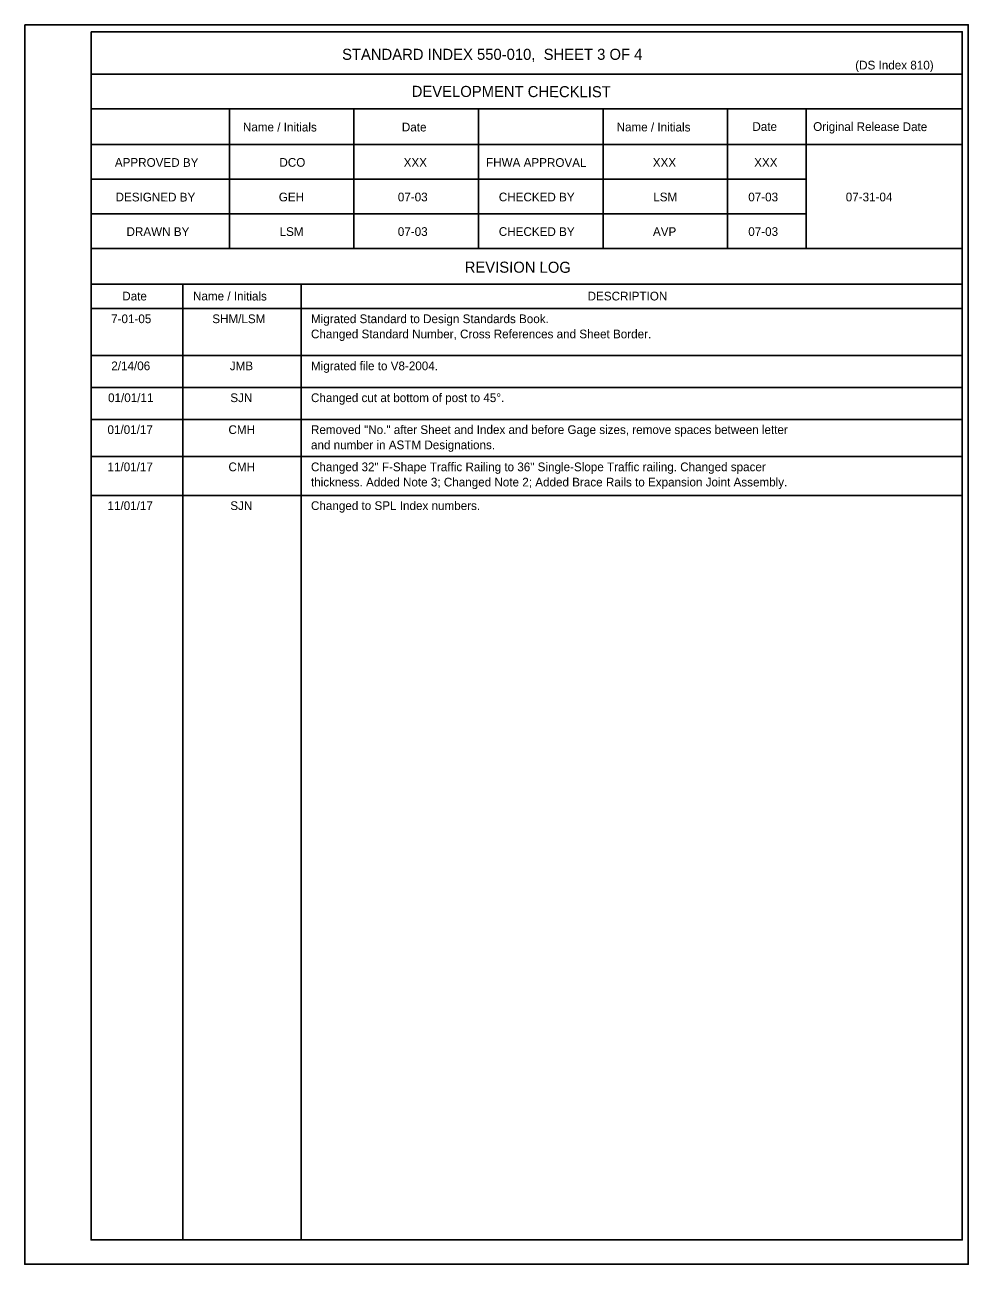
# Model space of a CAD drawing. Extents: x 0 to 72.1, y -7 to 30.
# Drawn here: x 50.31 to 72.12, y -0.65 to 28.01 of the extents above; entities that cross this region are included whole.
import ezdxf

# ---------------------------------------------------------------- set-up
doc = ezdxf.new("R2010")
doc.units = 0
for name, color, linetype in [('Border', 7, 'Continuous'), ('PlotBorder_dp', 7, 'Continuous'), ('TextStructures', 7, 'Continuous')]:
    doc.layers.add(name, color=color, linetype=linetype)

msp = doc.modelspace()

# ---------------------------------------------------------------- linework, layer by layer
at = {"layer": 'Border'}
for p, q in [((71.988, 26.871), (51.841, 26.871)), ((71.988, 26.071), (51.841, 26.071)), ((55.041, 26.071), (55.041, 22.843)), ((57.921, 26.071), (57.921, 22.843)), ((60.801, 26.071), (60.801, 22.843)), ((63.681, 26.071), (63.681, 22.843)), ((66.561, 26.071), (66.561, 22.843)), ((68.376, 26.071), (68.376, 22.843)), ((71.988, 25.243), (51.841, 25.243)), ((68.376, 24.443), (51.841, 24.443)), ((68.376, 23.643), (51.841, 23.643)), ((71.988, 22.843), (51.841, 22.843)), ((71.988, 22.015), (51.841, 22.015)), ((53.962, 22.015), (53.962, -0.091)), ((56.704, 22.015), (56.704, -0.091)), ((71.988, 21.451), (51.841, 21.451)), ((71.988, 20.362), (51.841, 20.362)), ((71.988, 19.625), (51.841, 19.625)), ((71.988, 18.887), (51.841, 18.887)), ((71.988, 18.026), (51.841, 18.026)), ((71.988, 17.129), (51.841, 17.129))]:
    msp.add_line(p, q, dxfattribs=at)
msp.add_lwpolyline([(51.842, 27.851), (71.988, 27.851), (71.988, -0.091), (51.842, -0.091)], close=True, dxfattribs=at)
at = {"layer": 'PlotBorder_dp'}
msp.add_line((50.311, -0.653), (50.311, -0.653), dxfattribs=at)
msp.add_lwpolyline([(50.311, 28.014), (72.124, 28.014), (72.124, -0.653), (50.311, -0.653)], close=True, dxfattribs=at)

# ---------------------------------------------------------------- texts
at = {"layer": 'TextStructures'}
for s, height, p in [('STANDARD INDEX 550-010,  SHEET 3 OF 4', 0.256, (57.647, 27.203)), ('(DS Index 810)', 0.2016, (69.512, 26.98)), ('DCO', 0.2016, (56.198, 24.73)), ('XXX', 0.2016, (59.071, 24.73)), ('XXX', 0.2016, (64.831, 24.73)), ('XXX', 0.2016, (67.175, 24.73)), ('GEH', 0.2016, (56.184, 23.93)), ('07-03', 0.2016, (58.936, 23.93)), ('LSM', 0.2016, (64.842, 23.93)), ('07-03', 0.2016, (67.039, 23.93)), ('07-31-04', 0.2016, (69.293, 23.93)), ('LSM', 0.2016, (56.202, 23.13)), ('07-03', 0.2016, (58.936, 23.13)), ('AVP', 0.2016, (64.835, 23.13)), ('07-03', 0.2016, (67.039, 23.13)), ('DESCRIPTION', 0.2016, (63.325, 21.638)), ('7-01-05', 0.2016, (52.307, 21.113)), ('SHM/LSM', 0.2016, (54.646, 21.113)), ('Migrated Standard to Design Standards Book.', 0.2016, (56.928, 21.113)), ('Changed Standard Number, Cross References and Sheet Border.', 0.2016, (56.928, 20.762)), ('2/14/06', 0.2016, (52.311, 20.024)), ('JMB', 0.2016, (55.051, 20.024)), ('Migrated file to V8-2004.', 0.2016, (56.928, 20.024)), ('01/01/11', 0.2016, (52.236, 19.287)), ('Changed cut at bottom of post to 45°.', 0.2016, (56.928, 19.287)), ('SJN', 0.2016, (55.063, 19.287)), ('01/01/17', 0.2016, (52.223, 18.549)), ('CMH', 0.2016, (55.02, 18.549)), ('Removed "No." after Sheet and Index and before Gage sizes, remove spaces between letter', 0.2016, (56.928, 18.549)), ('and number in ASTM Designations.', 0.2016, (56.928, 18.197)), ('11/01/17', 0.2016, (52.223, 17.688)), ('CMH', 0.2016, (55.02, 17.688)), ('Changed 32" F-Shape Traffic Railing to 36" Single-Slope Traffic railing. Changed spacer', 0.2016, (56.928, 17.688)), ('thickness. Added Note 3; Changed Note 2; Added Brace Rails to Expansion Joint Assembly.', 0.2016, (56.928, 17.336)), ('11/01/17', 0.2016, (52.223, 16.791)), ('SJN', 0.2016, (55.063, 16.791)), ('Changed to SPL Index numbers.', 0.2016, (56.928, 16.791))]:
    msp.add_text(s, height=height, dxfattribs=at).set_placement(p)
for s, height, p in [('DEVELOPMENT CHECKLIST', 0.256, (59.257, 26.347)), ('Name / Initials', 0.2016, (55.354, 25.55)), ('Date', 0.2016, (59.029, 25.548)), ('Name / Initials', 0.2016, (63.994, 25.55)), ('Date', 0.2016, (67.134, 25.56)), ('Original Release Date', 0.2016, (68.54, 25.56)), ('APPROVED BY', 0.2016, (52.393, 24.731)), ('FHWA APPROVAL', 0.2016, (60.976, 24.731)), ('DESIGNED BY', 0.2016, (52.41, 23.93)), ('CHECKED BY', 0.2016, (61.271, 23.931)), ('DRAWN BY', 0.2016, (52.663, 23.13)), ('CHECKED BY', 0.2016, (61.271, 23.131)), ('REVISION LOG', 0.256, (60.482, 22.282)), ('Date', 0.2016, (52.564, 21.639)), ('Name / Initials', 0.2016, (54.2, 21.64))]:
    msp.add_text(s, height=height, rotation=359.8756, dxfattribs=at).set_placement(p)

doc.saveas('drawing.dxf')
